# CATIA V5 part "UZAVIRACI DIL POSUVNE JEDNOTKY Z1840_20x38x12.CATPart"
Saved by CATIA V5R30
Part number: UZAVIRACI DIL POSUVNE JEDNOTKY MENSI
Bounding box of the stored display mesh (mm): x -65 to 0, y -41 to 0, z -19 to 19
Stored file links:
  C:\Users\ondra\Desktop\PŘÍLOHA P III\CATIA\UZAVIRACI DIL POSUVNE JEDNOTKY Z1840_20x38x12.CATPart
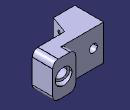
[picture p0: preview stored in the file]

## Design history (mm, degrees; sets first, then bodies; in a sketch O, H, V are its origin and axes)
Set1
  DatumSurface1 to DatumSurface45 "Z1840/20"
  Plane1: type Tangent, Support DatumSurface27, RefPoint vertex [face of DatumSurface31]
  Plane2: type Tangent, Support DatumSurface28, RefPoint vertex [face of DatumSurface31]
  Plane3: type Tangent, Support DatumSurface31, RefPoint vertex [face of DatumSurface31]
  Plane4: type Tangent, Support DatumSurface26, RefPoint vertex [face of DatumSurface25]
  Plane5: type Tangent, Support DatumSurface26, RefPoint vertex [face of DatumSurface25]
  Point1: type OnSurface, Support DatumSurface23, Length 0, Direction edge of DatumSurface24
  Plane6: type Tangent, Support DatumSurface23, RefPoint Point1
  Point2: type OnSurface, Support DatumSurface23, Length 0, Direction edge of DatumSurface24
  Plane7: type Tangent, Support DatumSurface23, RefPoint Point2
  Point3: type OnSurface, Support DatumSurface19, Length 0, Direction edge of DatumSurface18
  Plane8: type Tangent, Support DatumSurface19, RefPoint Point3
  Join1: Elements (DatumSurface1; DatumSurface2; DatumSurface3; DatumSurface4; DatumSurface5; DatumSurface6; DatumSurface7; DatumSurface8; DatumSurface9; DatumSurface10; DatumSurface11; DatumSurface12; DatumSurface13; DatumSurface14; DatumSurface15; DatumSurface16; DatumSurface17; DatumSurface18; DatumSurface19; DatumSurface20; DatumSurface21; DatumSurface22; DatumSurface23; DatumSurface24; DatumSurface25; DatumSurface26; DatumSurface27; DatumSurface28; DatumSurface29; DatumSurface30; DatumSurface31; DatumSurface32; DatumSurface33; DatumSurface34; DatumSurface35; DatumSurface36; DatumSurface37; DatumSurface38; DatumSurface39; DatumSurface40; DatumSurface41; DatumSurface42; DatumSurface43; DatumSurface44; DatumSurface45)
Body1 (main body)
  CloseSurface1: CloseElement Join1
